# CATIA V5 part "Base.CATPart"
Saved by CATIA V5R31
Part number: Part1
Bounding box of the stored display mesh (mm): x -50 to 50, y -25 to 25, z 0 to 50
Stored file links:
  D:\PROJECTS\Project 2021\US EDITION\CATIA V5 6R 2021\Resources\Part Files\c12_catia_v5_6r2021_prt\c12_catia_v5-6r2021 figr_12-8\Base.CATPart
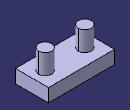
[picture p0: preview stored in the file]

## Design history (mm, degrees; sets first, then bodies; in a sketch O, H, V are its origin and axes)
Body1 (main body)
  Sketch1 on xy-plane, origin (0, 0, 0), H (1, 0, 0), V (0, 1, 0)
    line L1 (50, 25) -> (50, -25)
    line L2 (50, -25) -> (-50, -25)
    line L3 (-50, -25) -> (-50, 25)
    line L4 (-50, 25) -> (50, 25)
    circle A1 centre (-30, 0) radius 10
    point P5 (-30, 0)
    circle A2 centre (30, 0) radius 10
    length L2 = 100
    length L1 = 50
    radius A1 = 10
    distance P5 V = 30
    vertical: L1 V, L3 V
    horizontal: L2 H, L4 H
    equidistance: L1 L3 O, L2 L4 O
    coincidence: P5 H
    symmetry: A1 A2 V
  MultiPad1: profile Sketch1, domains (length 20; length 50; length 50)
